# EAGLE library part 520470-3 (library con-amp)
AMP connector
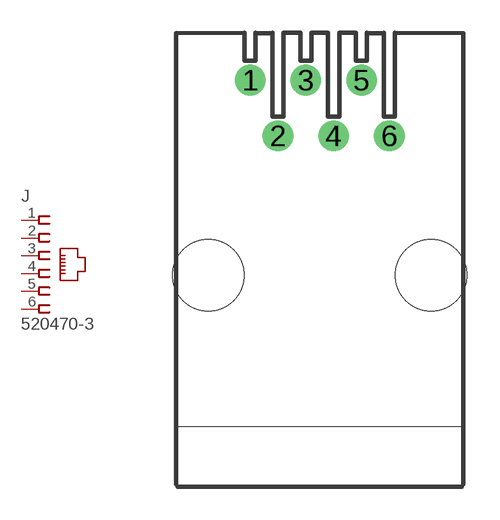
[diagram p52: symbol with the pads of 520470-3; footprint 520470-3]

Designator prefix J

## 520470-3 (MF: TYCO ELECTRONICS; MPN: 5520470-3; OC_FARNELL: 1087500; OC_NEWARK: 42K7233)  [520470-3]
1  1  pas
2  2  pas
3  3  pas
4  4  pas
5  5  pas
6  6  pas

## Footprint 520470-3 (pad centres in mm)
Modular Jack without Panel Stops
drill 0.889 round: 1 -3.175,8.89; 2 -1.905,6.35; 3 -0.635,8.89; 4 0.635,6.35; 5 1.905,8.89; 6 3.175,6.35
hole 3.251 at -5.08,0
hole 3.251 at 5.08,0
